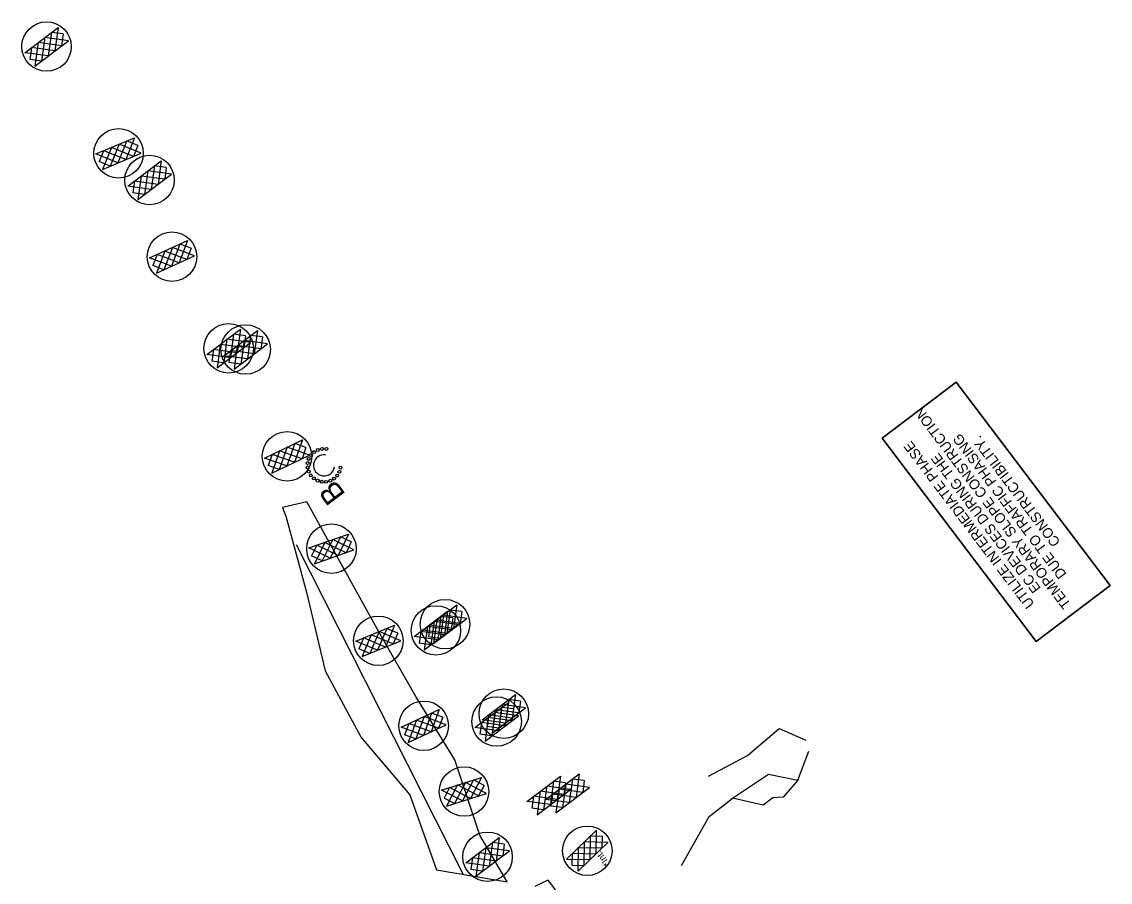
# Model space of a CAD drawing. Extents: x 400935 to 481562, y 415700 to 505362.
# Drawn here: x 476010 to 476760, y 500920 to 501512 of the extents above; entities that cross this region are included whole.
import ezdxf

# ---------------------------------------------------------------- set-up
doc = ezdxf.new("R2010")
doc.units = 0
for name, color, linetype in [('Excelsior Wattle Line Style Final', 7, 'Continuous'), ('Label B CG CELL', 7, 'Continuous'), ('Matting on Slope Note Final CELL', 7, 'Continuous'), ('Old_Level_2', 7, 'Continuous'), ('Prop Grid Mask', 7, 'Continuous'), ('Rock Pipe Inlet Sediment Trap Type B CG CELL', 7, 'Continuous'), ('Rock Silt Check Type A CG CELL', 7, 'Continuous'), ('Rock Silt Check Type A Final CELL', 7, 'Continuous'), ('Rock Silt Check Type A with Matting and PAM CG CELL', 7, 'Continuous'), ('Rock Silt Check Type A with Matting and PAM Final CELL', 7, 'Continuous'), ('Temporary Silt Fence Both', 7, 'Continuous'), ('Temporary Silt Fence CG', 7, 'Continuous'), ('Temporary Silt Fence Final', 7, 'Continuous')]:
    doc.layers.add(name, color=color, linetype=linetype)

msp = doc.modelspace()

# ---------------------------------------------------------------- linework, layer by layer
at = {"layer": 'Excelsior Wattle Line Style Final'}
msp.add_line((476314.3, 500925.15), (476199.35, 501151.96), dxfattribs=at)
at = {"layer": 'Matting on Slope Note Final CELL'}
for p, q in [((476206.62, 501181.5), (476189.69, 501177.74)), ((476189.69, 501177.74), (476192.06, 501171.72)), ((476192.06, 501171.72), (476206.22, 501119.37)), ((476206.22, 501119.37), (476219.06, 501065.28)), ((476219.06, 501065.28), (476244.01, 501019.35)), ((476244.01, 501019.35), (476277.58, 500979.78)), ((476277.58, 500979.78), (476295.96, 500928.06)), ((476295.96, 500928.06), (476344.58, 500919.9)), ((476372.57, 500921.11), (476363.61, 500916.7))]:
    msp.add_line(p, q, dxfattribs=at)
msp.add_lwpolyline([(476344.58, 500919.9), (476325.6, 500951.97), (476308.48, 501003.83), (476281.56, 501047.53), (476256.25, 501092.19), (476231.39, 501136.93), (476206.62, 501181.5)], dxfattribs=at)
msp.add_arc((477416.95, 501716.88), 1313, 217.30549, 218.24077, dxfattribs=at)
at = {"layer": 'Old_Level_2'}
for p, q in [((476406.09, 500955.6), (476385.31, 500935.52)), ((476405.81, 500939.27), (476406.09, 500955.6)), ((476414.12, 500947.3), (476393.34, 500927.21)), ((476397.52, 500931.23), (476397.78, 500947.58)), ((476397.78, 500947.58), (476414.12, 500947.3)), ((476401.64, 500935.24), (476401.96, 500951.61)), ((476401.96, 500951.61), (476410.13, 500951.44)), ((476409.98, 500943.37), (476410.13, 500951.44)), ((476389.33, 500931.34), (476389.48, 500939.55)), ((476389.48, 500939.55), (476405.81, 500939.27)), ((476393.34, 500927.21), (476393.61, 500943.54)), ((476393.61, 500943.54), (476409.98, 500943.3)), ((476385.31, 500935.52), (476401.64, 500935.24)), ((476389.33, 500931.34), (476397.52, 500931.23))]:
    msp.add_line(p, q, dxfattribs=at)
msp.add_lwpolyline([(476759.95, 501123.97), (476653.89, 501264.09), (476602.93, 501225.52), (476708.99, 501085.4)], close=True, dxfattribs=at)
msp.add_circle((476399.77, 500941.29), 17.04, dxfattribs=at)
at = {"layer": 'Prop Grid Mask'}
msp.add_lwpolyline([(476708.99, 501085.4), (476602.93, 501225.52), (476653.89, 501264.09), (476759.95, 501123.97)], close=True, dxfattribs=at)
at = {"layer": 'Rock Pipe Inlet Sediment Trap Type B CG CELL'}
for centre in [(476211.52, 501215.84), (476214.11, 501217.31), (476217, 501218.06), (476219.98, 501218.04), (476207.1, 501208.29), (476207.89, 501211.17), (476209.4, 501213.74), (476207.08, 501205.31), (476207.83, 501202.43), (476209.3, 501199.83), (476227.43, 501199.71), (476228.94, 501202.29), (476229.73, 501205.16), (476211.4, 501197.71), (476213.97, 501196.2), (476216.85, 501195.41), (476219.83, 501195.39), (476222.71, 501196.14), (476225.31, 501197.62)]:
    msp.add_circle(centre, 1.01, dxfattribs=at)
msp.add_arc((476218.41, 501206.73), 7.26, 82.1231, 352.11428, dxfattribs=at)
at = {"layer": 'Rock Silt Check Type A CG CELL'}
for p, q in [((476371.16, 500976.72), (476394.21, 500994.17)), ((476389.58, 500990.68), (476387.34, 500974.49)), ((476397.69, 500989.59), (476389.58, 500990.68)), ((476394.21, 500994.17), (476391.97, 500977.99)), ((476378.14, 500967.52), (476401.18, 500984.96)), ((476380.37, 500983.7), (476378.14, 500967.52)), ((476396.55, 500981.46), (476380.37, 500983.7)), ((476385, 500987.2), (476382.72, 500970.99)), ((476401.18, 500984.96), (476385, 500987.2)), ((476397.69, 500989.59), (476396.55, 500981.46)), ((476387.34, 500974.49), (476371.16, 500976.72)), ((476375.74, 500980.13), (476374.62, 500972.13)), ((476391.97, 500977.99), (476375.75, 500980.2)), ((476382.72, 500970.99), (476374.62, 500972.13))]:
    msp.add_line(p, q, dxfattribs=at)
at = {"layer": 'Rock Silt Check Type A Final CELL'}
for p, q in [((476358.13, 500975.33), (476381.17, 500992.77)), ((476381.17, 500992.77), (476378.93, 500976.59)), ((476365.1, 500966.12), (476388.14, 500983.56)), ((476371.96, 500985.8), (476369.68, 500969.59)), ((476388.14, 500983.56), (476371.96, 500985.8)), ((476376.54, 500989.28), (476374.31, 500973.09)), ((476384.65, 500988.19), (476376.54, 500989.28)), ((476384.65, 500988.19), (476383.51, 500980.06)), ((476374.31, 500973.09), (476358.13, 500975.33)), ((476362.7, 500978.73), (476361.59, 500970.73)), ((476378.93, 500976.59), (476362.71, 500978.8)), ((476367.33, 500982.3), (476365.1, 500966.12)), ((476383.51, 500980.06), (476367.33, 500982.3)), ((476369.68, 500969.59), (476361.59, 500970.73))]:
    msp.add_line(p, q, dxfattribs=at)
at = {"layer": 'Rock Silt Check Type A with Matting and PAM CG CELL'}
for p, q in [((476083.23, 501398.97), (476106.27, 501416.42)), ((476101.64, 501412.93), (476099.41, 501396.74)), ((476109.75, 501411.84), (476101.64, 501412.93)), ((476106.27, 501416.42), (476104.03, 501400.24)), ((476109.75, 501411.84), (476108.62, 501403.71)), ((476090.2, 501389.76), (476113.24, 501407.21)), ((476092.44, 501405.94), (476090.2, 501389.76)), ((476108.62, 501403.71), (476092.44, 501405.94)), ((476097.06, 501409.45), (476094.78, 501393.24)), ((476113.24, 501407.21), (476097.06, 501409.45)), ((476099.41, 501396.74), (476083.23, 501398.97)), ((476087.8, 501402.37), (476086.69, 501394.38)), ((476104.03, 501400.24), (476087.81, 501402.44)), ((476094.78, 501393.24), (476086.69, 501394.38)), ((476149.44, 501282.27), (476172.48, 501299.71)), ((476172.48, 501299.71), (476170.24, 501283.53)), ((476156.41, 501273.06), (476179.45, 501290.5)), ((476163.27, 501292.74), (476160.99, 501276.53)), ((476179.45, 501290.5), (476163.27, 501292.74)), ((476167.85, 501296.22), (476165.62, 501280.03)), ((476175.96, 501295.13), (476167.85, 501296.22)), ((476175.96, 501295.13), (476174.83, 501287)), ((476154.01, 501285.67), (476152.9, 501277.67)), ((476170.24, 501283.53), (476154.02, 501285.74)), ((476158.65, 501289.24), (476156.41, 501273.06)), ((476174.83, 501287), (476158.65, 501289.24)), ((476165.62, 501280.03), (476149.44, 501282.27)), ((476160.99, 501276.53), (476152.9, 501277.67)), ((476286.78, 501093.14), (476309.82, 501110.58)), ((476309.82, 501110.58), (476307.58, 501094.4)), ((476300.61, 501103.61), (476298.33, 501087.4)), ((476316.79, 501101.37), (476300.61, 501103.61)), ((476305.19, 501107.09), (476302.96, 501090.9)), ((476313.3, 501106), (476305.19, 501107.09)), ((476313.3, 501106), (476312.17, 501097.87)), ((476291.35, 501096.54), (476290.24, 501088.55)), ((476307.58, 501094.4), (476291.36, 501096.61)), ((476293.75, 501083.93), (476316.79, 501101.37)), ((476295.99, 501100.11), (476293.75, 501083.93)), ((476312.17, 501097.87), (476295.99, 501100.11)), ((476302.96, 501090.9), (476286.78, 501093.14)), ((476298.33, 501087.4), (476290.24, 501088.55)), ((476327.25, 501031.45), (476350.29, 501048.89)), ((476345.66, 501045.4), (476343.43, 501029.21)), ((476353.77, 501044.32), (476345.66, 501045.4)), ((476350.29, 501048.89), (476348.05, 501032.71)), ((476353.77, 501044.32), (476352.64, 501036.18)), ((476334.22, 501022.24), (476357.26, 501039.68)), ((476336.46, 501038.42), (476334.22, 501022.24)), ((476352.64, 501036.18), (476336.46, 501038.42)), ((476341.08, 501041.92), (476338.81, 501025.71)), ((476357.26, 501039.68), (476341.08, 501041.92)), ((476343.43, 501029.21), (476327.25, 501031.45)), ((476331.83, 501034.85), (476330.71, 501026.86)), ((476348.05, 501032.71), (476331.83, 501034.92)), ((476338.81, 501025.71), (476330.71, 501026.86))]:
    msp.add_line(p, q, dxfattribs=at)
for centre in [(476098.19, 501403.22), (476164.4, 501286.51), (476301.74, 501097.38), (476342.21, 501035.7)]:
    msp.add_circle(centre, 17.04, dxfattribs=at)
at = {"layer": 'Rock Silt Check Type A with Matting and PAM Final CELL'}
for p, q in [((476012.26, 501490.93), (476035.31, 501508.37)), ((476035.31, 501508.37), (476033.07, 501492.19)), ((476026.1, 501501.4), (476023.82, 501485.19)), ((476042.28, 501499.16), (476026.1, 501501.4)), ((476030.67, 501504.88), (476028.44, 501488.69)), ((476038.79, 501503.8), (476030.67, 501504.88)), ((476038.79, 501503.8), (476037.65, 501495.66)), ((476016.84, 501494.33), (476015.72, 501486.34)), ((476033.07, 501492.19), (476016.85, 501494.4)), ((476019.23, 501481.72), (476042.28, 501499.16)), ((476021.47, 501497.9), (476019.23, 501481.72)), ((476037.65, 501495.66), (476021.47, 501497.9)), ((476028.44, 501488.69), (476012.26, 501490.93)), ((476023.82, 501485.19), (476015.72, 501486.34)), ((476061.31, 501421.19), (476087.95, 501432.39)), ((476071.96, 501425.66), (476065.78, 501410.54)), ((476077.3, 501427.91), (476071.08, 501412.77)), ((476087.08, 501419.49), (476071.96, 501425.66)), ((476082.6, 501430.15), (476076.43, 501415.02)), ((476092.42, 501421.74), (476077.3, 501427.91)), ((476087.95, 501432.39), (476081.78, 501417.26)), ((476090.19, 501427.09), (476082.6, 501430.15)), ((476090.19, 501427.09), (476087.08, 501419.49)), ((476076.43, 501415.02), (476061.31, 501421.19)), ((476066.58, 501423.35), (476063.52, 501415.88)), ((476065.78, 501410.54), (476092.42, 501421.74)), ((476081.78, 501417.26), (476066.61, 501423.42)), ((476071.08, 501412.77), (476063.52, 501415.88)), ((476098.13, 501349.54), (476124.44, 501361.51)), ((476119.15, 501359.12), (476113.42, 501343.81)), ((476124.44, 501361.51), (476118.7, 501346.21)), ((476126.83, 501356.28), (476119.15, 501359.12)), ((476103.34, 501351.86), (476100.5, 501344.3)), ((476108.64, 501354.32), (476102.91, 501339.03)), ((476102.91, 501339.03), (476129.22, 501350.99)), ((476118.7, 501346.21), (476103.36, 501351.92)), ((476113.92, 501356.73), (476108.14, 501341.41)), ((476123.94, 501348.59), (476108.64, 501354.32)), ((476129.22, 501350.99), (476113.92, 501356.73)), ((476126.83, 501356.28), (476123.94, 501348.59)), ((476113.42, 501343.81), (476098.13, 501349.54)), ((476108.14, 501341.41), (476100.5, 501344.3)), ((476137.72, 501283.07), (476160.76, 501300.51)), ((476160.76, 501300.51), (476158.52, 501284.33)), ((476144.69, 501273.86), (476167.73, 501291.3)), ((476151.55, 501293.54), (476149.27, 501277.33)), ((476167.73, 501291.3), (476151.55, 501293.54)), ((476156.13, 501297.02), (476153.9, 501280.83)), ((476164.24, 501295.93), (476156.13, 501297.02)), ((476164.24, 501295.93), (476163.11, 501287.8)), ((476153.9, 501280.83), (476137.72, 501283.07)), ((476142.29, 501286.47), (476141.18, 501278.48)), ((476158.52, 501284.33), (476142.3, 501286.54)), ((476146.93, 501290.04), (476144.69, 501273.86)), ((476163.11, 501287.8), (476146.93, 501290.04)), ((476149.27, 501277.33), (476141.18, 501278.48)), ((476177.4, 501211.77), (476203.47, 501224.24)), ((476203.47, 501224.24), (476198.03, 501208.84)), ((476187.82, 501216.75), (476182.38, 501201.35)), ((476193.05, 501219.26), (476187.57, 501203.83)), ((476203.22, 501211.32), (476187.82, 501216.75)), ((476198.23, 501221.75), (476192.8, 501206.33)), ((476208.45, 501213.82), (476193.05, 501219.26)), ((476205.96, 501219.06), (476198.23, 501221.75)), ((476205.96, 501219.06), (476203.22, 501211.32)), ((476192.8, 501206.33), (476177.4, 501211.77)), ((476182.56, 501214.18), (476179.87, 501206.58)), ((476182.38, 501201.35), (476208.45, 501213.82)), ((476198.03, 501208.84), (476182.58, 501214.25)), ((476187.57, 501203.83), (476179.87, 501206.58)), ((476207.95, 501149.92), (476235.25, 501159.38)), ((476224.34, 501155.6), (476217.16, 501140.89)), ((476229.77, 501157.49), (476222.64, 501142.78)), ((476239.03, 501148.46), (476224.34, 501155.6)), ((476235.25, 501159.38), (476228.12, 501144.68)), ((476237.15, 501153.95), (476229.77, 501157.49)), ((476222.64, 501142.78), (476207.95, 501149.92)), ((476213.35, 501151.74), (476209.82, 501144.48)), ((476218.86, 501153.7), (476211.73, 501139)), ((476211.73, 501139), (476239.03, 501148.46)), ((476228.12, 501144.68), (476213.38, 501151.8)), ((476233.55, 501146.56), (476218.86, 501153.7)), ((476237.15, 501153.95), (476233.55, 501146.56)), ((476217.16, 501140.89), (476209.82, 501144.48)), ((476280.5, 501088.8), (476303.54, 501106.24)), ((476298.91, 501102.75), (476296.68, 501086.56)), ((476307.02, 501101.67), (476298.91, 501102.75)), ((476303.54, 501106.24), (476301.3, 501090.06)), ((476240.25, 501085.7), (476267.02, 501096.59)), ((476267.02, 501096.59), (476260.67, 501081.54)), ((476287.47, 501079.59), (476310.51, 501097.04)), ((476289.71, 501095.77), (476287.47, 501079.59)), ((476305.89, 501093.54), (476289.71, 501095.77)), ((476294.33, 501099.27), (476292.06, 501083.06)), ((476310.51, 501097.04), (476294.33, 501099.27)), ((476307.02, 501101.67), (476305.89, 501093.54)), ((476245.55, 501087.8), (476242.4, 501080.37)), ((476250.95, 501090.05), (476244.6, 501075)), ((476260.67, 501081.54), (476245.57, 501087.87)), ((476256.32, 501092.24), (476249.93, 501077.17)), ((476266, 501083.71), (476250.95, 501090.05)), ((476261.64, 501094.42), (476255.3, 501079.35)), ((476271.37, 501085.89), (476256.32, 501092.24)), ((476269.19, 501091.27), (476261.64, 501094.42)), ((476269.19, 501091.27), (476266, 501083.71)), ((476296.68, 501086.56), (476280.5, 501088.8)), ((476285.08, 501092.2), (476283.96, 501084.21)), ((476301.3, 501090.06), (476285.08, 501092.27)), ((476255.3, 501079.35), (476240.25, 501085.7)), ((476249.93, 501077.17), (476242.4, 501080.37)), ((476244.6, 501075), (476271.37, 501085.89)), ((476292.06, 501083.06), (476283.96, 501084.21)), ((476322.32, 501026.08), (476345.36, 501043.52)), ((476345.36, 501043.52), (476343.13, 501027.34)), ((476271.52, 501026.45), (476297.77, 501038.54)), ((476292.5, 501036.13), (476286.85, 501020.79)), ((476297.77, 501038.54), (476292.12, 501023.22)), ((476300.19, 501033.33), (476292.5, 501036.13)), ((476336.15, 501036.55), (476333.88, 501020.34)), ((476352.33, 501034.31), (476336.15, 501036.55)), ((476340.73, 501040.03), (476338.5, 501023.84)), ((476348.84, 501038.94), (476340.73, 501040.03)), ((476348.84, 501038.94), (476347.71, 501030.81)), ((476276.72, 501028.79), (476273.92, 501021.22)), ((476282.02, 501031.28), (476276.36, 501015.96)), ((476276.36, 501015.96), (476302.61, 501028.05)), ((476292.12, 501023.22), (476276.75, 501028.86)), ((476287.28, 501033.71), (476281.58, 501018.37)), ((476297.34, 501025.63), (476282.02, 501031.28)), ((476302.61, 501028.05), (476287.28, 501033.71)), ((476300.19, 501033.33), (476297.34, 501025.63)), ((476326.9, 501029.48), (476325.78, 501021.49)), ((476343.13, 501027.34), (476326.91, 501029.55)), ((476329.29, 501016.87), (476352.33, 501034.31)), ((476331.53, 501033.05), (476329.29, 501016.87)), ((476347.71, 501030.81), (476331.53, 501033.05)), ((476286.85, 501020.79), (476271.52, 501026.45)), ((476281.58, 501018.37), (476273.92, 501021.22)), ((476338.5, 501023.84), (476322.32, 501026.08)), ((476333.88, 501020.34), (476325.78, 501021.49)), ((476299.31, 500983.12), (476326.87, 500991.83)), ((476326.87, 500991.83), (476319.34, 500977.33)), ((476313.81, 500975.58), (476299.31, 500983.12)), ((476304.76, 500984.79), (476301.04, 500977.63)), ((476310.33, 500986.6), (476302.8, 500972.1)), ((476319.34, 500977.33), (476304.8, 500984.85)), ((476315.86, 500988.35), (476308.28, 500973.84)), ((476324.82, 500979.07), (476310.33, 500986.6)), ((476321.34, 500990.09), (476313.81, 500975.58)), ((476330.35, 500980.81), (476315.86, 500988.35)), ((476328.62, 500986.35), (476321.34, 500990.09)), ((476328.62, 500986.35), (476324.82, 500979.07)), ((476308.28, 500973.84), (476301.04, 500977.63)), ((476302.8, 500972.1), (476330.35, 500980.81)), ((476316.07, 500932.94), (476339.11, 500950.38)), ((476334.48, 500946.89), (476332.25, 500930.7)), ((476342.59, 500945.8), (476334.48, 500946.89)), ((476339.11, 500950.38), (476336.87, 500934.2)), ((476342.59, 500945.8), (476341.46, 500937.67)), ((476323.04, 500923.73), (476346.08, 500941.17)), ((476325.28, 500939.91), (476323.04, 500923.73)), ((476341.46, 500937.67), (476325.28, 500939.91)), ((476329.9, 500943.41), (476327.62, 500927.2)), ((476346.08, 500941.17), (476329.9, 500943.41)), ((476332.25, 500930.7), (476316.07, 500932.94)), ((476320.64, 500936.34), (476319.53, 500928.35)), ((476336.87, 500934.2), (476320.65, 500936.41)), ((476327.62, 500927.2), (476319.53, 500928.35))]:
    msp.add_line(p, q, dxfattribs=at)
for centre in [(476027.23, 501495.17), (476076.86, 501421.6), (476113.66, 501350.4), (476152.68, 501287.31), (476192.91, 501212.93), (476223.49, 501149.32), (476255.8, 501085.93), (476295.46, 501093.05), (476287.05, 501027.39), (476337.28, 501030.32), (476314.84, 500982.1), (476331.03, 500937.18)]:
    msp.add_circle(centre, 17.04, dxfattribs=at)
at = {"layer": 'Temporary Silt Fence Both'}
for points in [[(476483.22, 500992.7), (476483.22, 500992.7), (476510.17, 501006.86), (476531.87, 501025.51), (476550.29, 501017.38)], [(476544.82, 500990.03), (476544.82, 500990.03), (476552.44, 501009.79)], [(476464.53, 500931.19), (476483.6, 500964.95), (476496.02, 500974.59), (476499.8, 500977.53)]]:
    msp.add_lwpolyline(points, dxfattribs=at)
at = {"layer": 'Temporary Silt Fence CG'}
msp.add_lwpolyline([(476499.8, 500977.53), (476524.63, 500994.07), (476544.82, 500990.03)], dxfattribs=at)
at = {"layer": 'Temporary Silt Fence Final'}
msp.add_lwpolyline([(476544.82, 500990.03), (476534.69, 500978.18), (476527.57, 500977.67), (476520.87, 500972.7), (476499.8, 500977.53)], dxfattribs=at)

# ---------------------------------------------------------------- texts
at = {"layer": 'Label B CG CELL'}
msp.add_text('B', height=15, rotation=127.12364, dxfattribs=at).set_placement((476233.69, 501186.83))
at = {"layer": 'Old_Level_2'}
for s, height, rotation, p in [('TEMPORARY SLOPE CONSTRUCTION', 7, 127.12309, (476733.27, 501111.2)), ('UTILIZE INTERMEDIATE PHASE', 7, 127.12309, (476708.07, 501111.36)), ('DUE TO TRAFFIC PHASING', 7, 127.12309, (476730.19, 501131.84)), ('CONSTRUCTIBILITY.', 7, 127.12309, (476725.98, 501153.97)), ('EC DEVICES DURING THE ', 7, 127.12309, (476712.49, 501122.09)), ('*Int.', 4.746, 127.12364, (476415.53, 500932.88))]:
    msp.add_text(s, height=height, rotation=rotation, dxfattribs=at).set_placement(p)

doc.saveas('drawing.dxf')
